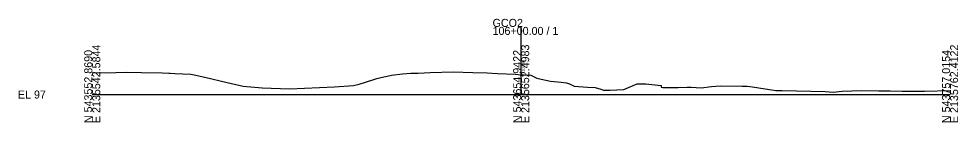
# Model space of a CAD drawing. Extents: x -14327 to 8886, y -10 to 39048.
# Drawn here: x 3974.3 to 4302.8, y 31990.3 to 32026.5 of the extents above; entities that cross this region are included whole.
import ezdxf

# ---------------------------------------------------------------- set-up
doc = ezdxf.new("R2010")
doc.units = 0
for name, color, linetype in [('RD_GPK_XS_Cell', 7, 'Continuous'), ('RD_XS_ExGround', 7, 'Continuous'), ('RD_XS_TX_Elev_EX', 7, 'Continuous')]:
    doc.layers.add(name, color=color, linetype=linetype)

msp = doc.modelspace()

# ---------------------------------------------------------------- linework, layer by layer
at = {"layer": 'RD_GPK_XS_Cell'}
for p, q in [((4150, 32000), (4150, 32023.67)), ((4000, 32000), (4150, 32000)), ((4150, 32000), (4300, 32000))]:
    msp.add_line(p, q, dxfattribs=at)
at = {"layer": 'RD_XS_ExGround'}
for p, q in [((4000, 32007.59), (4000.2, 32007.6)), ((4000.2, 32007.6), (4008.3, 32007.76)), ((4008.3, 32007.76), (4011.96, 32007.86)), ((4011.96, 32007.86), (4017.21, 32007.72)), ((4017.21, 32007.72), (4024.48, 32007.55)), ((4024.48, 32007.55), (4026.77, 32007.45)), ((4026.77, 32007.45), (4027.25, 32007.43)), ((4027.25, 32007.43), (4028.92, 32007.35)), ((4028.92, 32007.35), (4034.44, 32007.1)), ((4034.44, 32007.1), (4035.62, 32006.85)), ((4035.62, 32006.85), (4039.32, 32006.07)), ((4039.32, 32006.07), (4047.18, 32004.24)), ((4099.52, 32005.61), (4100.91, 32005.99)), ((4100.91, 32005.99), (4104.23, 32006.71)), ((4104.23, 32006.71), (4104.63, 32006.8)), ((4104.63, 32006.8), (4108.44, 32007.19)), ((4108.44, 32007.19), (4111.44, 32007.45)), ((4111.44, 32007.45), (4112.89, 32007.5)), ((4112.89, 32007.5), (4113.99, 32007.53)), ((4113.99, 32007.53), (4118.22, 32007.66)), ((4118.22, 32007.66), (4126.26, 32007.89)), ((4126.26, 32007.89), (4133.14, 32007.69)), ((4133.14, 32007.69), (4138.05, 32007.54)), ((4138.05, 32007.54), (4141.77, 32007.37)), ((4141.77, 32007.37), (4147.85, 32007.08)), ((4147.85, 32007.08), (4150, 32006.94)), ((4150, 32006.94), (4150.36, 32006.92)), ((4150.36, 32006.92), (4151.04, 32006.87)), ((4151.04, 32006.87), (4153.43, 32006.79)), ((4153.43, 32006.79), (4155.5, 32005.76)), ((4155.5, 32005.76), (4155.94, 32005.66)), ((4155.94, 32005.66), (4160.28, 32004.62)), ((4047.18, 32004.24), (4052.75, 32002.94)), ((4052.75, 32002.94), (4059.44, 32002.39)), ((4059.44, 32002.39), (4069.03, 32001.99)), ((4069.03, 32001.99), (4084.75, 32002.72)), ((4084.75, 32002.72), (4091.31, 32003.14)), ((4091.31, 32003.14), (4091.85, 32003.29)), ((4091.85, 32003.29), (4093.4, 32003.67)), ((4093.4, 32003.67), (4098.46, 32005.26)), ((4098.46, 32005.26), (4099.52, 32005.61)), ((4160.28, 32004.62), (4163.95, 32004.27)), ((4163.95, 32004.27), (4165.86, 32004.13)), ((4165.86, 32004.13), (4166.86, 32003.7)), ((4166.86, 32003.7), (4168.58, 32002.96)), ((4168.58, 32002.96), (4173.21, 32002.63)), ((4173.21, 32002.63), (4175.86, 32002.49)), ((4175.86, 32002.49), (4177.84, 32001.86)), ((4185.86, 32001.71), (4189.2, 32003.17)), ((4189.2, 32003.17), (4190.61, 32003.75)), ((4190.61, 32003.75), (4191.19, 32003.75)), ((4191.19, 32003.75), (4193.54, 32003.72)), ((4193.54, 32003.72), (4198.99, 32003.16)), ((4198.99, 32003.16), (4199, 32002.63)), ((4199, 32002.63), (4199.54, 32002.48)), ((4199.54, 32002.48), (4202.26, 32002.47)), ((4202.26, 32002.47), (4202.79, 32002.47)), ((4202.79, 32002.47), (4203.66, 32002.49)), ((4203.66, 32002.49), (4204.89, 32002.5)), ((4204.89, 32002.5), (4208.07, 32002.58)), ((4208.07, 32002.58), (4209.02, 32002.6)), ((4209.02, 32002.6), (4209.48, 32002.56)), ((4209.48, 32002.56), (4212.99, 32002.29)), ((4212.99, 32002.29), (4216.51, 32002.77)), ((4216.51, 32002.77), (4219.54, 32003.06)), ((4219.54, 32003.06), (4227.27, 32002.95)), ((4227.27, 32002.95), (4229.04, 32002.93)), ((4229.04, 32002.93), (4230.93, 32002.68)), ((4230.93, 32002.68), (4239.04, 32001.36)), ((4177.84, 32001.86), (4178.81, 32001.53)), ((4178.81, 32001.53), (4180.98, 32001.57)), ((4180.98, 32001.57), (4185.86, 32001.71)), ((4239.04, 32001.36), (4241.24, 32001.39)), ((4241.24, 32001.39), (4256.27, 32001.09)), ((4256.27, 32001.09), (4259.06, 32000.88)), ((4259.06, 32000.88), (4262.2, 32001.13)), ((4262.2, 32001.13), (4269.06, 32001.37)), ((4269.06, 32001.37), (4275.07, 32001.33)), ((4275.07, 32001.33), (4279.07, 32001.32)), ((4279.07, 32001.32), (4283.23, 32001.15)), ((4283.23, 32001.15), (4291.04, 32001.23)), ((4291.04, 32001.23), (4300, 32001.46))]:
    msp.add_line(p, q, dxfattribs=at)

# ---------------------------------------------------------------- texts
at = {"layer": 'RD_GPK_XS_Cell'}
for s, p in [('GCO2', (4140, 32023.67)), ('106+00.00 / 1', (4140, 32020.87)), ('EL 97', (3974, 31998.6))]:
    msp.add_text(s, height=2.8, dxfattribs=at).set_placement(p)
for s, p in [('E 2135542.5844', (4002.8, 31990)), ('E 2135652.4983', (4152.8, 31990)), ('E 2135762.4122', (4302.8, 31990)), ('N 543552.8690', (4000, 31990)), ('N 543654.9422', (4150, 31990)), ('N 543757.0154', (4300, 31990))]:
    msp.add_text(s, height=2.8, rotation=90, dxfattribs=at).set_placement(p)
at = {"layer": 'RD_XS_TX_Elev_EX'}
msp.add_text('103.94', height=1, rotation=90, dxfattribs=at).set_placement((4151.25, 32007.94))

doc.saveas('drawing.dxf')
